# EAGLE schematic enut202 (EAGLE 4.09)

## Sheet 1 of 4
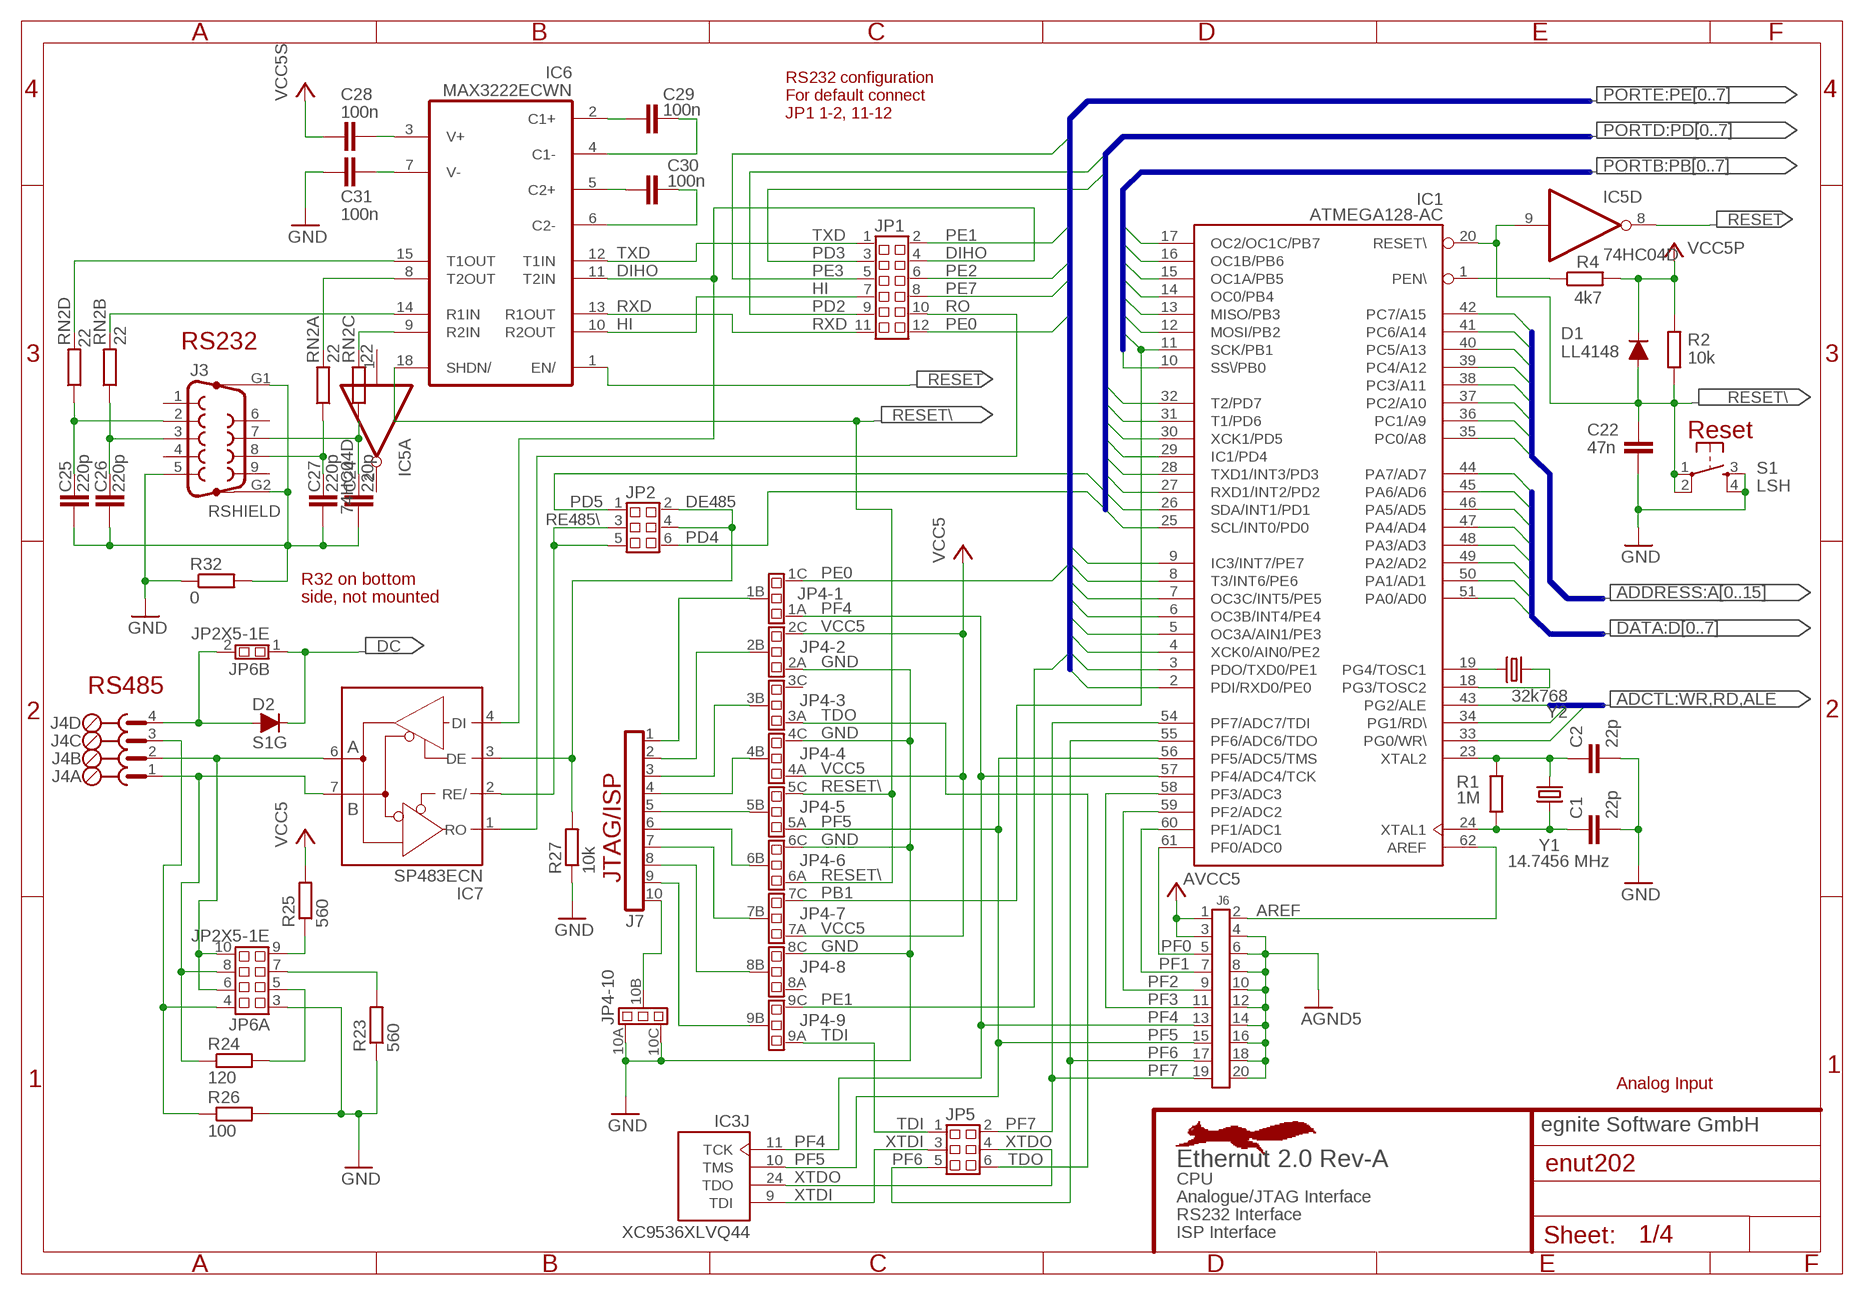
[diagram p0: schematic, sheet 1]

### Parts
C1  22p  C0603  [C0603]
C2  22p  C0603  [C0603]
C22  47n  C0603  [C0603]
C24  220p  C0603  [C0603]
C25  220p  C0603  [C0603]
C26  220p  C0603  [C0603]
C27  220p  C0603  [C0603]
C28  100n  C0603  [C0603]
C29  100n  C0603  [C0603]
C30  100n  C0603  [C0603]
C31  100n  C0603  [C0603]
D1  LL4148  [SOD-80C]
D2  S1G  [SMB]
IC1  ATMEGA128-AC  [TQFP64]
IC3  XC9536XLVQ44  [VQFP44]
IC5  74HC04D  [SO14]
IC6  MAX3222ECWN  [SO18W]
IC7  SP483ECN  [SOIC8]
J3  SUBD9F  [SUBD9F]
J4  MINISK  [MINISK]
J6  PIN2X10-2.54  [SLLP2X10]
J7  ML10A  [ML10A]
JP1  JP2X6  [SLY2X6]
JP2  JP2X3  [SLY2X3]
JP4  JP10X3  [SLY3X10]
JP5  JP2X3  [SLY2X3]
JP6  JP2X5-1E  [SLY2X5]
R1  1M  R0603  [R0603]
R2  10k  R0603  [R0603]
R4  4k7  R0603  [R0603]
R23  560  R1206  [R1206]
R24  120  R1206  [R1206]
R25  560  R1206  [R1206]
R26  100  R1206  [R1206]
R27  10k  R0603  [R0603]
R32  0  R0603  [R0603]
RN2  22  CAY16  [CAY16]
S1  LSH  [LSH]
Y1  14.7456 MHz  CRYSTALHC49SM  [HC49SM]
Y2  32k768  CRYSTAL-TC38  [TC38]

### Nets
A8 [AddrbusH]: IC1.35(PC0/A8) ; also sheet 2
A9 [AddrbusH]: IC1.36(PC1/A9) ; also sheet 2
A10 [AddrbusH]: IC1.37(PC2/A10) ; also sheet 2
A11 [AddrbusH]: IC1.38(PC3/A11) ; also sheet 2
A12 [AddrbusH]: IC1.39(PC4/A12) ; also sheet 2
A13 [AddrbusH]: IC1.40(PC5/A13) ; also sheet 2
A14 [AddrbusH]: IC1.41(PC6/A14) ; also sheet 2
A15 [AddrbusH]: IC1.42(PC7/A15) ; also sheet 2
AGND5: J6.4 J6.6 J6.8 J6.10 J6.12 J6.14 J6.16 J6.18 J6.20 ; also sheet 4
ALE: IC1.43(PG2/ALE) ; also sheet 2
AREF: IC1.62(AREF) J6.2
AVCC5: J6.1 J6.3 ; also sheet 4
D0 [Databus]: IC1.51(PA0/AD0) ; also sheet 2,3
D1 [Databus]: IC1.50(PA1/AD1) ; also sheet 2,3
D2 [Databus]: IC1.49(PA2/AD2) ; also sheet 2,3
D3 [Databus]: IC1.48(PA3/AD3) ; also sheet 2,3
D4 [Databus]: IC1.47(PA4/AD4) ; also sheet 2,3
D5 [Databus]: IC1.46(PA5/AD5) ; also sheet 2,3
D6 [Databus]: IC1.45(PA6/AD6) ; also sheet 2,3
D7 [Databus]: IC1.44(PA7/AD7) ; also sheet 2,3
DC: D2.C JP6.1 ; also sheet 2,4
DCX: D2.A J4.4 JP6.2
DE485: IC7.3(DE) JP2.2 JP2.4 R27.2
DIHO: IC6.11(T2IN) IC7.4(DI) JP1.4
GND: C1.2 C2.2 C22.2 C31.1 J3.5 JP4.2A(-2:A) JP4.4C(-4:C) JP4.6C(-6:C) JP4.8C(-8:C) JP4.10A(-10:A) JP4.10C(-10:C) JP6.3 R23.1 R26.2 R27.1 R32.1 S1.3(S) S1.4(S1) ; also sheet 2,3,4
HI: IC6.10(R2OUT) JP1.7
N$1: C28.2 IC6.3(V+)
N$6: C2.1 IC1.23(XTAL2) R1.2 Y1.P$2
N$7: IC1.19(PG4/TOSC1) Y2.2
N$10: C1.1 IC1.24(XTAL1) R1.1 Y1.P$1
N$15: C31.2 IC6.7(V-)
N$20: JP6.9 R25.1
N$21: J7.1 JP4.1B(-1:B)
N$23: IC1.18(PG3/TOSC2) Y2.1
N$31: C29.1 IC6.2(C1+)
N$38: J7.2 JP4.2B(-2:B)
N$45: J7.4 JP4.4B(-4:B)
N$48: J7.5 JP4.5B(-5:B)
N$49: J7.6 JP4.6B(-6:B)
N$50: J7.7 JP4.7B(-7:B)
N$51: J7.8 JP4.8B(-8:B)
N$52: J7.9 JP4.9B(-9:B)
N$56: C29.2 IC6.4(C1-)
N$57: C30.2 IC6.6(C2-)
N$58: C30.1 IC6.5(C2+)
N$59: J4.3 JP6.4 R26.1
N$60: C24.1 J3.7 RN2.3
N$61: C27.1 J3.8 RN2.1
N$62: C25.1 J3.2 RN2.4
N$63: C26.1 J3.3 RN2.2
N$65: IC6.15(T1OUT) RN2.5
N$66: IC6.8(T2OUT) RN2.8
N$67: IC6.14(R1IN) RN2.7
N$68: JP6.7 R23.2
N$69: IC6.9(R2IN) RN2.6
N$70: JP6.5 R24.2
N$73: J7.10 JP4.10B(-10:B)
PB0: IC1.10(SS\/PB0) ; also sheet 2
PB1: IC1.11(SCK/PB1) JP4.7C(-7:C) ; also sheet 2
PB2: IC1.12(MOSI/PB2) ; also sheet 2
PB3: IC1.13(MISO/PB3) ; also sheet 2
PB4: IC1.14(OC0/PB4) ; also sheet 2
PB5: IC1.15(OC1A/PB5) ; also sheet 2
PB6: IC1.16(OC1B/PB6) ; also sheet 2
PB7: IC1.17(OC2/OC1C/PB7) ; also sheet 2
PD0: IC1.25(SCL/INT0/PD0) ; also sheet 2
PD1: IC1.26(SDA/INT1/PD1) ; also sheet 2
PD2: IC1.27(RXD1/INT2/PD2) JP1.9 ; also sheet 2
PD3: IC1.28(TXD1/INT3/PD3) JP1.3 ; also sheet 2
PD4: IC1.29(IC1/PD4) JP2.6 ; also sheet 2
PD5: IC1.30(XCK1/PD5) JP2.1 ; also sheet 2
PD6: IC1.31(T1/PD6) ; also sheet 2
PD7: IC1.32(T2/PD7) ; also sheet 2
PE0: IC1.2(PDI/RXD0/PE0) JP1.12 JP4.1C(-1:C) ; also sheet 2
PE1: IC1.3(PDO/TXD0/PE1) JP1.2 JP4.9C(-9:C) ; also sheet 2
PE2: IC1.4(XCK0/AIN0/PE2) JP1.6 ; also sheet 2
PE3: IC1.5(OC3A/AIN1/PE3) JP1.5 ; also sheet 2,3
PE4: IC1.6(OC3B/INT4/PE4) ; also sheet 2
PE5: IC1.7(OC3C/INT5/PE5) ; also sheet 2,3
PE6: IC1.8(T3/INT6/PE6) ; also sheet 2
PE7: IC1.9(IC3/INT7/PE7) JP1.8 ; also sheet 2,3
PEN\: IC1.1(PEN\) R4.1
PF0: IC1.61(PF0/ADC0) J6.5
PF1: IC1.60(PF1/ADC1) J6.7
PF2: IC1.59(PF2/ADC2) J6.9
PF3: IC1.58(PF3/ADC3) J6.11
PF4: IC1.57(PF4/ADC4/TCK) IC3.11(TCK) J6.13 JP4.1A(-1:A)
PF5: IC1.56(PF5/ADC5/TMS) IC3.10(TMS) J6.15 JP4.5A(-5:A)
PF6: IC1.55(PF6/ADC6/TDO) J6.17 JP5.5
PF7: IC1.54(PF7/ADC7/TDI) J6.19 JP5.2
RD\: IC1.34(PG1/RD\) ; also sheet 2,3
RE485\: IC7.2(RE/) JP2.3 JP2.5
RESET: IC5.8(D:O) IC6.1(EN/) ; also sheet 3
RESET\: C22.1 D1.A IC1.20(RESET\) IC5.9(D:I) IC6.18(SHDN/) JP4.5C(-5:C) JP4.6A(-6:A) R2.1 S1.1(P) S1.2(P1) ; also sheet 2
RO: IC7.1(RO) JP1.10
RS485A: IC7.6(A) J4.2 JP6.6 JP6.10
RS485B: IC7.7(B) J4.1 JP6.8 R24.1
RSHIELD: C24.2 C25.2 C26.2 C27.2 J3.G1 J3.G2 R32.2
RXD: IC6.13(R1OUT) JP1.11
TDI: JP4.9A(-9:A) JP5.1
TDO: JP4.3A(-3:A) JP5.6
TDOX: J7.3 JP4.3B(-3:B)
TXD: IC6.12(T1IN) JP1.1
VCC5: JP4.2C(-2:C) JP4.4A(-4:A) JP4.7A(-7:A) R25.2 ; also sheet 2,4
VCC5P: D1.C R2.2 R4.2 ; also sheet 4
VCC5S: C28.1 ; also sheet 4
WR\: IC1.33(PG0/WR\) ; also sheet 2,3
XTDI: IC3.9(TDI) JP5.3
XTDO: IC3.24(TDO) JP5.4
Unconnected: IC5.3(B:I) IC5.4(B:O) IC5.5(C:I) IC5.6(C:O) IC5.10(E:O) IC5.11(E:I) IC5.12(F:O) IC5.13(F:I) J3.1 J3.4 J3.6 J3.9 JP4.3C(-3:C) JP4.8A(-8:A)

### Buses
DATA:D[0..7]
ADDRESS:A[0..15]
ADCTL:WR\,RD\,ALE
PORTB:PB[0..7]
PORTD:PD[0..7]
PORTE:PE[0..7]

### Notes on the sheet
- RS232 configuration
- For default connect
- JP1 1-2, 11-12
- RS232
- Reset
- R32 on bottom
- side, not mounted
- RS485
- JTAG/ISP
- Analog Input
- egnite Software GmbH
- Ethernut 2.0 Rev-A
- CPU
- Analogue/JTAG Interface
- RS232 Interface
- ISP Interface

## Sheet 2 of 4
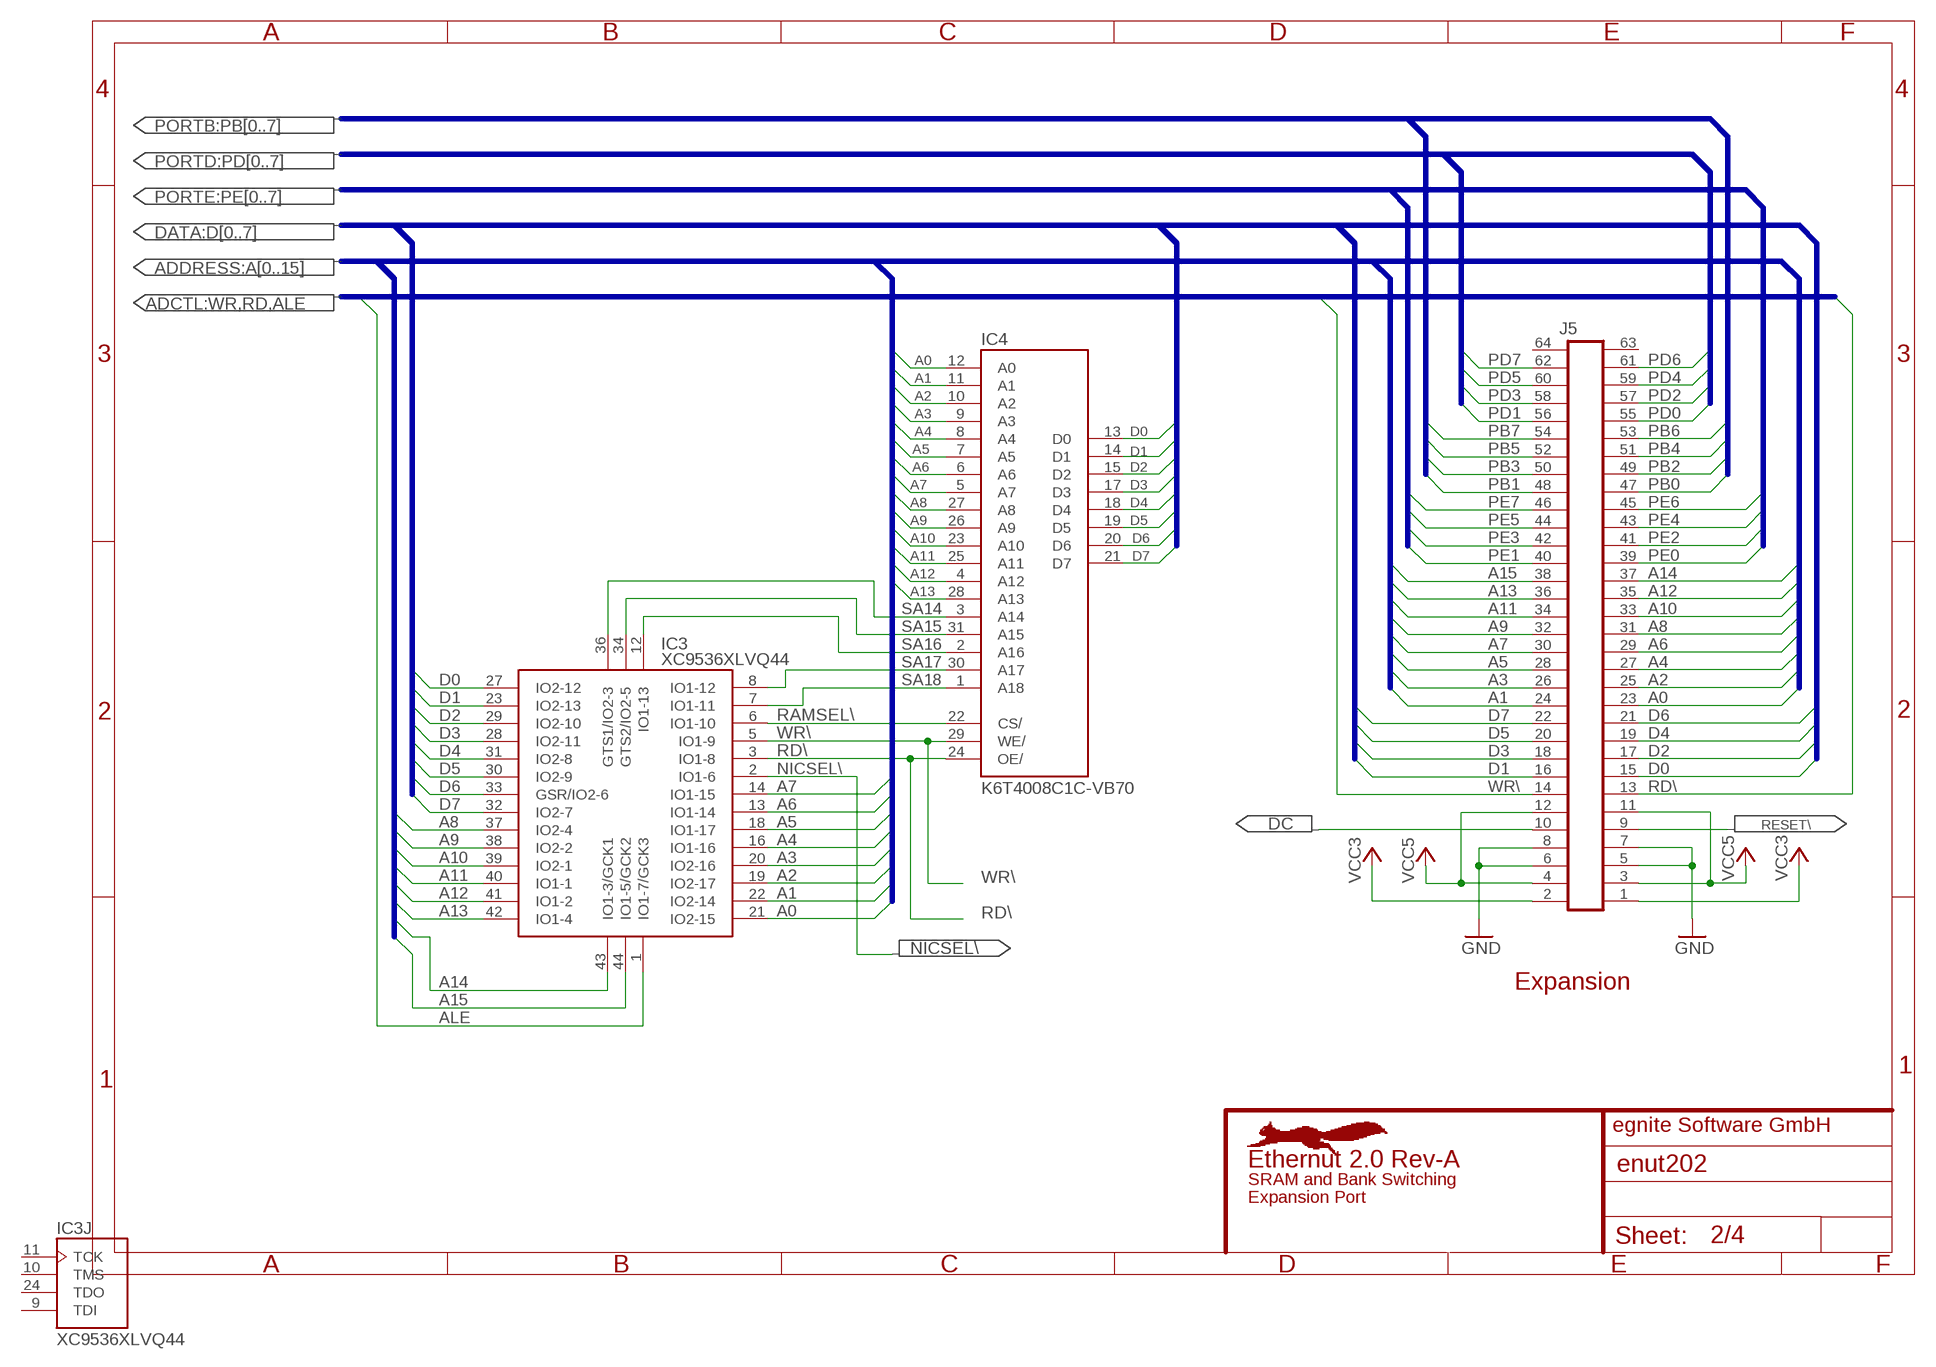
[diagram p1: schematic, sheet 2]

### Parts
IC4  K6T4008C1C-VB70  [TSOP2-32]
J5  NUTEXP  [NUTEXP]

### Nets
A0: IC3.21(IO2-15) IC4.12(A0) J5.23 ; also sheet 3
A1: IC3.22(IO2-14) IC4.11(A1) J5.24 ; also sheet 3
A2: IC3.19(IO2-17) IC4.10(A2) J5.25 ; also sheet 3
A3: IC3.20(IO2-16) IC4.9(A3) J5.26 ; also sheet 3
A4: IC3.16(IO1-16) IC4.8(A4) J5.27 ; also sheet 3
A5: IC3.18(IO1-17) IC4.7(A5) J5.28
A6: IC3.13(IO1-14) IC4.6(A6) J5.29
A7: IC3.14(IO1-15) IC4.5(A7) J5.30
A8 [AddrbusH]: IC3.37(IO2-4) IC4.27(A8) J5.31 ; also sheet 1
A9 [AddrbusH]: IC3.38(IO2-2) IC4.26(A9) J5.32 ; also sheet 1
A10 [AddrbusH]: IC3.39(IO2-1) IC4.23(A10) J5.33 ; also sheet 1
A11 [AddrbusH]: IC3.40(IO1-1) IC4.25(A11) J5.34 ; also sheet 1
A12 [AddrbusH]: IC3.41(IO1-2) IC4.4(A12) J5.35 ; also sheet 1
A13 [AddrbusH]: IC3.42(IO1-4) IC4.28(A13) J5.36 ; also sheet 1
A14 [AddrbusH]: IC3.43(IO1-3/GCK1) J5.37 ; also sheet 1
A15 [AddrbusH]: IC3.44(IO1-5/GCK2) J5.38 ; also sheet 1
ALE: IC3.1(IO1-7/GCK3) ; also sheet 1
D0 [Databus]: IC3.27(IO2-12) IC4.13(D0) J5.15 ; also sheet 1,3
D1 [Databus]: IC3.23(IO2-13) IC4.14(D1) J5.16 ; also sheet 1,3
D2 [Databus]: IC3.29(IO2-10) IC4.15(D2) J5.17 ; also sheet 1,3
D3 [Databus]: IC3.28(IO2-11) IC4.17(D3) J5.18 ; also sheet 1,3
D4 [Databus]: IC3.31(IO2-8) IC4.18(D4) J5.19 ; also sheet 1,3
D5 [Databus]: IC3.30(IO2-9) IC4.19(D5) J5.20 ; also sheet 1,3
D6 [Databus]: IC3.33(GSR/IO2-6) IC4.20(D6) J5.21 ; also sheet 1,3
D7 [Databus]: IC3.32(IO2-7) IC4.21(D7) J5.22 ; also sheet 1,3
DC: J5.10 ; also sheet 1,4
GND: J5.5 J5.6 J5.7 J5.8 ; also sheet 1,3,4
NICSEL\: IC3.2(IO1-6) ; also sheet 3
PB0: J5.47 ; also sheet 1
PB1: J5.48 ; also sheet 1
PB2: J5.49 ; also sheet 1
PB3: J5.50 ; also sheet 1
PB4: J5.51 ; also sheet 1
PB5: J5.52 ; also sheet 1
PB6: J5.53 ; also sheet 1
PB7: J5.54 ; also sheet 1
PD0: J5.55 ; also sheet 1
PD1: J5.56 ; also sheet 1
PD2: J5.57 ; also sheet 1
PD3: J5.58 ; also sheet 1
PD4: J5.59 ; also sheet 1
PD5: J5.60 ; also sheet 1
PD6: J5.61 ; also sheet 1
PD7: J5.62 ; also sheet 1
PE0: J5.39 ; also sheet 1
PE1: J5.40 ; also sheet 1
PE2: J5.41 ; also sheet 1
PE3: J5.42 ; also sheet 1,3
PE4: J5.43 ; also sheet 1
PE5: J5.44 ; also sheet 1,3
PE6: J5.45 ; also sheet 1
PE7: J5.46 ; also sheet 1,3
RAMSEL\: IC3.6(IO1-10) IC4.22(CS/)
RD\: IC3.3(IO1-8) IC4.24(OE/) J5.13 ; also sheet 1,3
RESET\: J5.9 ; also sheet 1
SA14: IC3.36(GTS1/IO2-3) IC4.3(A14)
SA15: IC3.34(GTS2/IO2-5) IC4.31(A15)
SA16: IC3.12(IO1-13) IC4.2(A16)
SA17: IC3.8(IO1-12) IC4.30(A17)
SA18: IC3.7(IO1-11) IC4.1(A18)
VCC3: J5.1 J5.2 ; also sheet 4
VCC5: J5.3 J5.4 J5.11 J5.12 ; also sheet 1,4
WR\: IC3.5(IO1-9) IC4.29(WE/) J5.14 ; also sheet 1,3
Unconnected: J5.63 J5.64

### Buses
ADDRESS:A[0..15]
DATA:D[0..7]
ADCTL:WR\,RD\,ALE
PORTE:PE[0..7]
PORTD:PD[0..7]
PORTB:PB[0..7]

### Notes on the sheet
- Expansion
- egnite Software GmbH
- Ethernut 2.0 Rev-A
- SRAM and Bank Switching
- Expansion Port

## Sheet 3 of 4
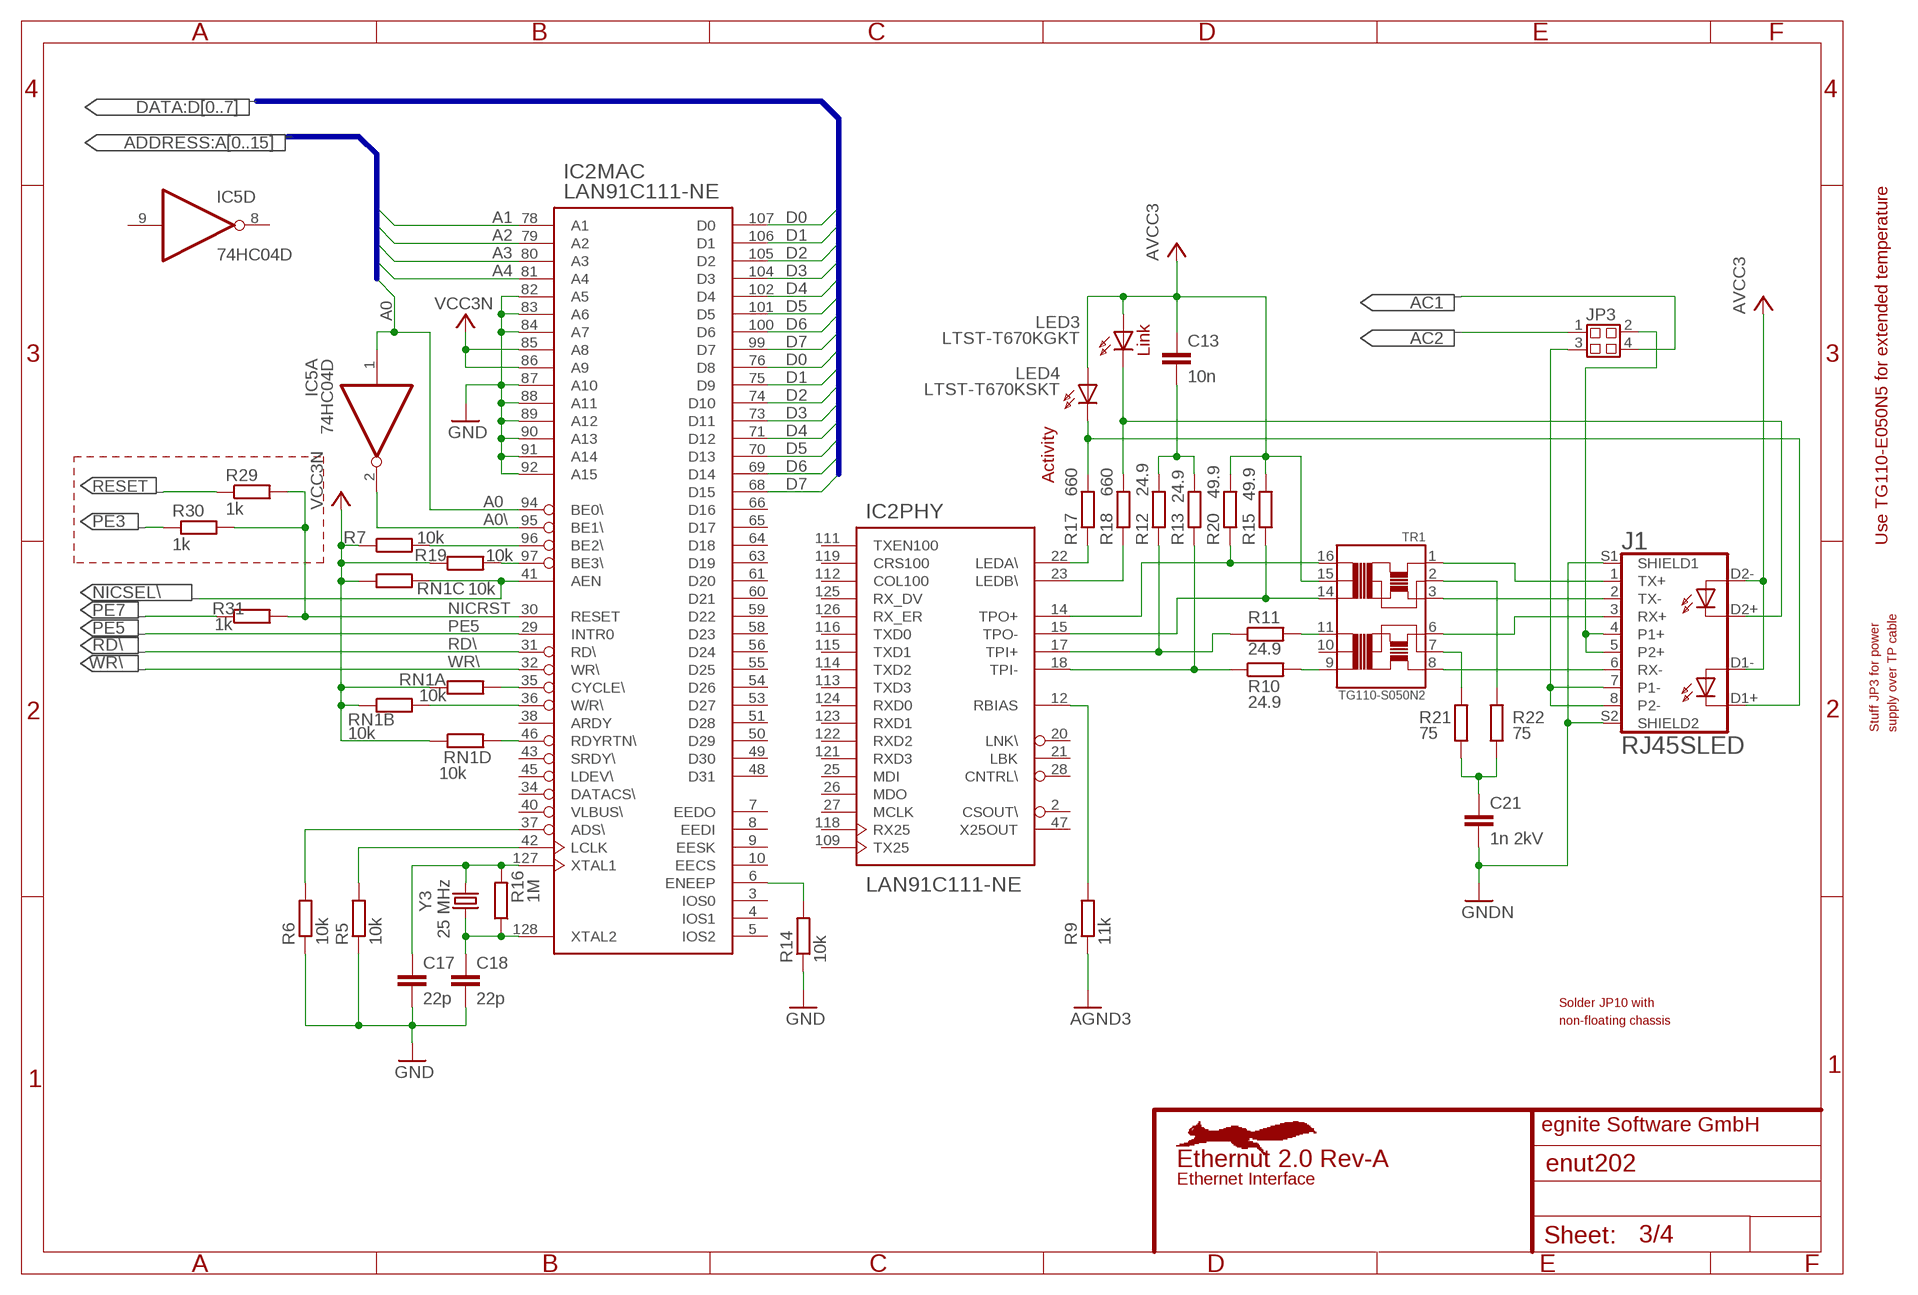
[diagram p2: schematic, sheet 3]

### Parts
C13  10n  C0603  [C0603]
C17  22p  C0603  [C0603]
C18  22p  C0603  [C0603]
C21  1n 2kV  C5.0  [C5.0]
IC2  LAN91C111-NE  [TQFP128]
J1  RJ45SLED  [RJ45S]
JP3  JP2X2  [SLY2X2]
LED3  LTST-T670KGKT  [P-LCC-2]
LED4  LTST-T670KSKT  [P-LCC-2]
R5  10k  R0603  [R0603]
R6  10k  R0603  [R0603]
R7  10k  R0603  [R0603]
R9  11k  R0603  [R0603]
R10  24.9  R0603  [R0603]
R11  24.9  R0603  [R0603]
R12  24.9  R0603  [R0603]
R13  24.9  R0603  [R0603]
R14  10k  R0603  [R0603]
R15  49.9  R0603  [R0603]
R16  1M  R0603  [R0603]
R17  660  R0603  [R0603]
R18  660  R0603  [R0603]
R19  10k  R0603  [R0603]
R20  49.9  R0603  [R0603]
R21  75  R1206  [R1206]
R22  75  R1206  [R1206]
R29  1k  R0603  [R0603]
R30  1k  R0603  [R0603]
R31  1k  R0603  [R0603]
RN1  10k  CAY16  [CAY16]
TR1  TG110-S050N2  [SOIC16-12TR]
Y3  25 MHz  CRYSTALHC49SM  [HC49SM]

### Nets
A0: IC2.94(MAC:BE0\) IC5.1(A:I) ; also sheet 2
A0\: IC2.95(MAC:BE1\) IC5.2(A:O)
A1: IC2.78(MAC:A1) ; also sheet 2
A2: IC2.79(MAC:A2) ; also sheet 2
A3: IC2.80(MAC:A3) ; also sheet 2
A4: IC2.81(MAC:A4) ; also sheet 2
AC1 [Supply1A]: JP3.4 ; also sheet 4
AC2 [Supply1A]: JP3.1 ; also sheet 4
AGND3: R9.1 ; also sheet 4
AVCC3: C13.1 J1.D1-(A1) J1.D2-(A2) LED3.A LED4.A R15.2 R20.2 TR1.15 ; also sheet 4
BE2\: IC2.96(MAC:BE2\) R7.2
CYCLE\: IC2.35(MAC:CYCLE\) RN1.8
D0 [Databus]: IC2.76(MAC:D8) IC2.107(MAC:D0) ; also sheet 1,2
D1 [Databus]: IC2.75(MAC:D9) IC2.106(MAC:D1) ; also sheet 1,2
D2 [Databus]: IC2.74(MAC:D10) IC2.105(MAC:D2) ; also sheet 1,2
D3 [Databus]: IC2.73(MAC:D11) IC2.104(MAC:D3) ; also sheet 1,2
D4 [Databus]: IC2.71(MAC:D12) IC2.102(MAC:D4) ; also sheet 1,2
D5 [Databus]: IC2.70(MAC:D13) IC2.101(MAC:D5) ; also sheet 1,2
D6 [Databus]: IC2.69(MAC:D14) IC2.100(MAC:D6) ; also sheet 1,2
D7 [Databus]: IC2.68(MAC:D15) IC2.99(MAC:D7) ; also sheet 1,2
ENEEP: IC2.6(MAC:ENEEP) R14.2
GND: C17.2 C18.2 IC2.82(MAC:A5) IC2.83(MAC:A6) IC2.84(MAC:A7) IC2.87(MAC:A10) IC2.88(MAC:A11) IC2.89(MAC:A12) IC2.90(MAC:A13) IC2.91(MAC:A14) IC2.92(MAC:A15) R5.1 R6.1 R14.1 ; also sheet 1,2,4
GNDN: C21.2 J1.S1(SHIELD1) J1.S2(SHIELD2)
LCLK: IC2.42(MAC:LCLK) R5.2
LEDA\: J1.D1+(C1) LED4.C R17.2
LEDB\: J1.D2+(C2) LED3.C R18.2
N$4: IC2.37(MAC:ADS\) R6.2
N$5: J1.1(TX+) TR1.1
N$12: J1.2(TX-) TR1.3
N$16: IC2.97(MAC:BE3\) R19.2
N$22: J1.3(RX+) TR1.6
N$24: J1.6(RX-) TR1.8
N$25: IC2.12(PHY:RBIAS) R9.2
N$26: R21.2 TR1.7
N$27: R10.2 TR1.9
N$32: R22.2 TR1.2
N$33: R11.2 TR1.11
N$44: C21.1 R21.1 R22.1
NICRST: IC2.30(MAC:RESET) R29.2 R30.2 R31.2
NICSEL\: IC2.41(MAC:AEN) RN1.6 ; also sheet 2
NICWR\: IC2.36(MAC:W/R\) RN1.7
NLEDA\: IC2.22(PHY:LEDA\) R17.1
NLEDB\: IC2.23(PHY:LEDB\) R18.1
NXTAL1: C17.1 IC2.127(MAC:XTAL1) R16.2 Y3.P$2
NXTAL2: C18.1 IC2.128(MAC:XTAL2) R16.1 Y3.P$1
PE3: R30.1 ; also sheet 1,2
PE5: IC2.29(MAC:INTR0) ; also sheet 1,2
PE7: R31.1 ; also sheet 1,2
POE+ [Supply1A]: J1.7(P1-) J1.8(P2-) JP3.3
POE- [Supply1A]: J1.4(P1+) J1.5(P2+) JP3.2
RD\: IC2.31(MAC:RD\) ; also sheet 1,2
RDYRTN\: IC2.46(MAC:RDYRTN\) RN1.5
RESET: R29.1 ; also sheet 1
RRCUP: C13.2 R12.2 R13.2
TPI+: IC2.17(PHY:TPI+) R11.1 R12.1
TPI-: IC2.18(PHY:TPI-) R10.1 R13.1
TPO+: IC2.14(PHY:TPO+) R20.1 TR1.16
TPO-: IC2.15(PHY:TPO-) R15.1 TR1.14
VCC3N: IC2.85(MAC:A8) IC2.86(MAC:A9) R7.1 R19.1 RN1.1 RN1.2 RN1.3 RN1.4 ; also sheet 4
WR\: IC2.32(MAC:WR\) ; also sheet 1,2
Unconnected: TR1.10

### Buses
DATA:D[0..7]
ADDRESS:A[0..15]

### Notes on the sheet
- Link
- Activity
- Use TG110-E050N5 for extended temperature
- Stuff JP3 for power | supply over TP cable
- Solder JP10 with
- non-floating chassis
- egnite Software GmbH
- Ethernut 2.0 Rev-A
- Ethernet Interface

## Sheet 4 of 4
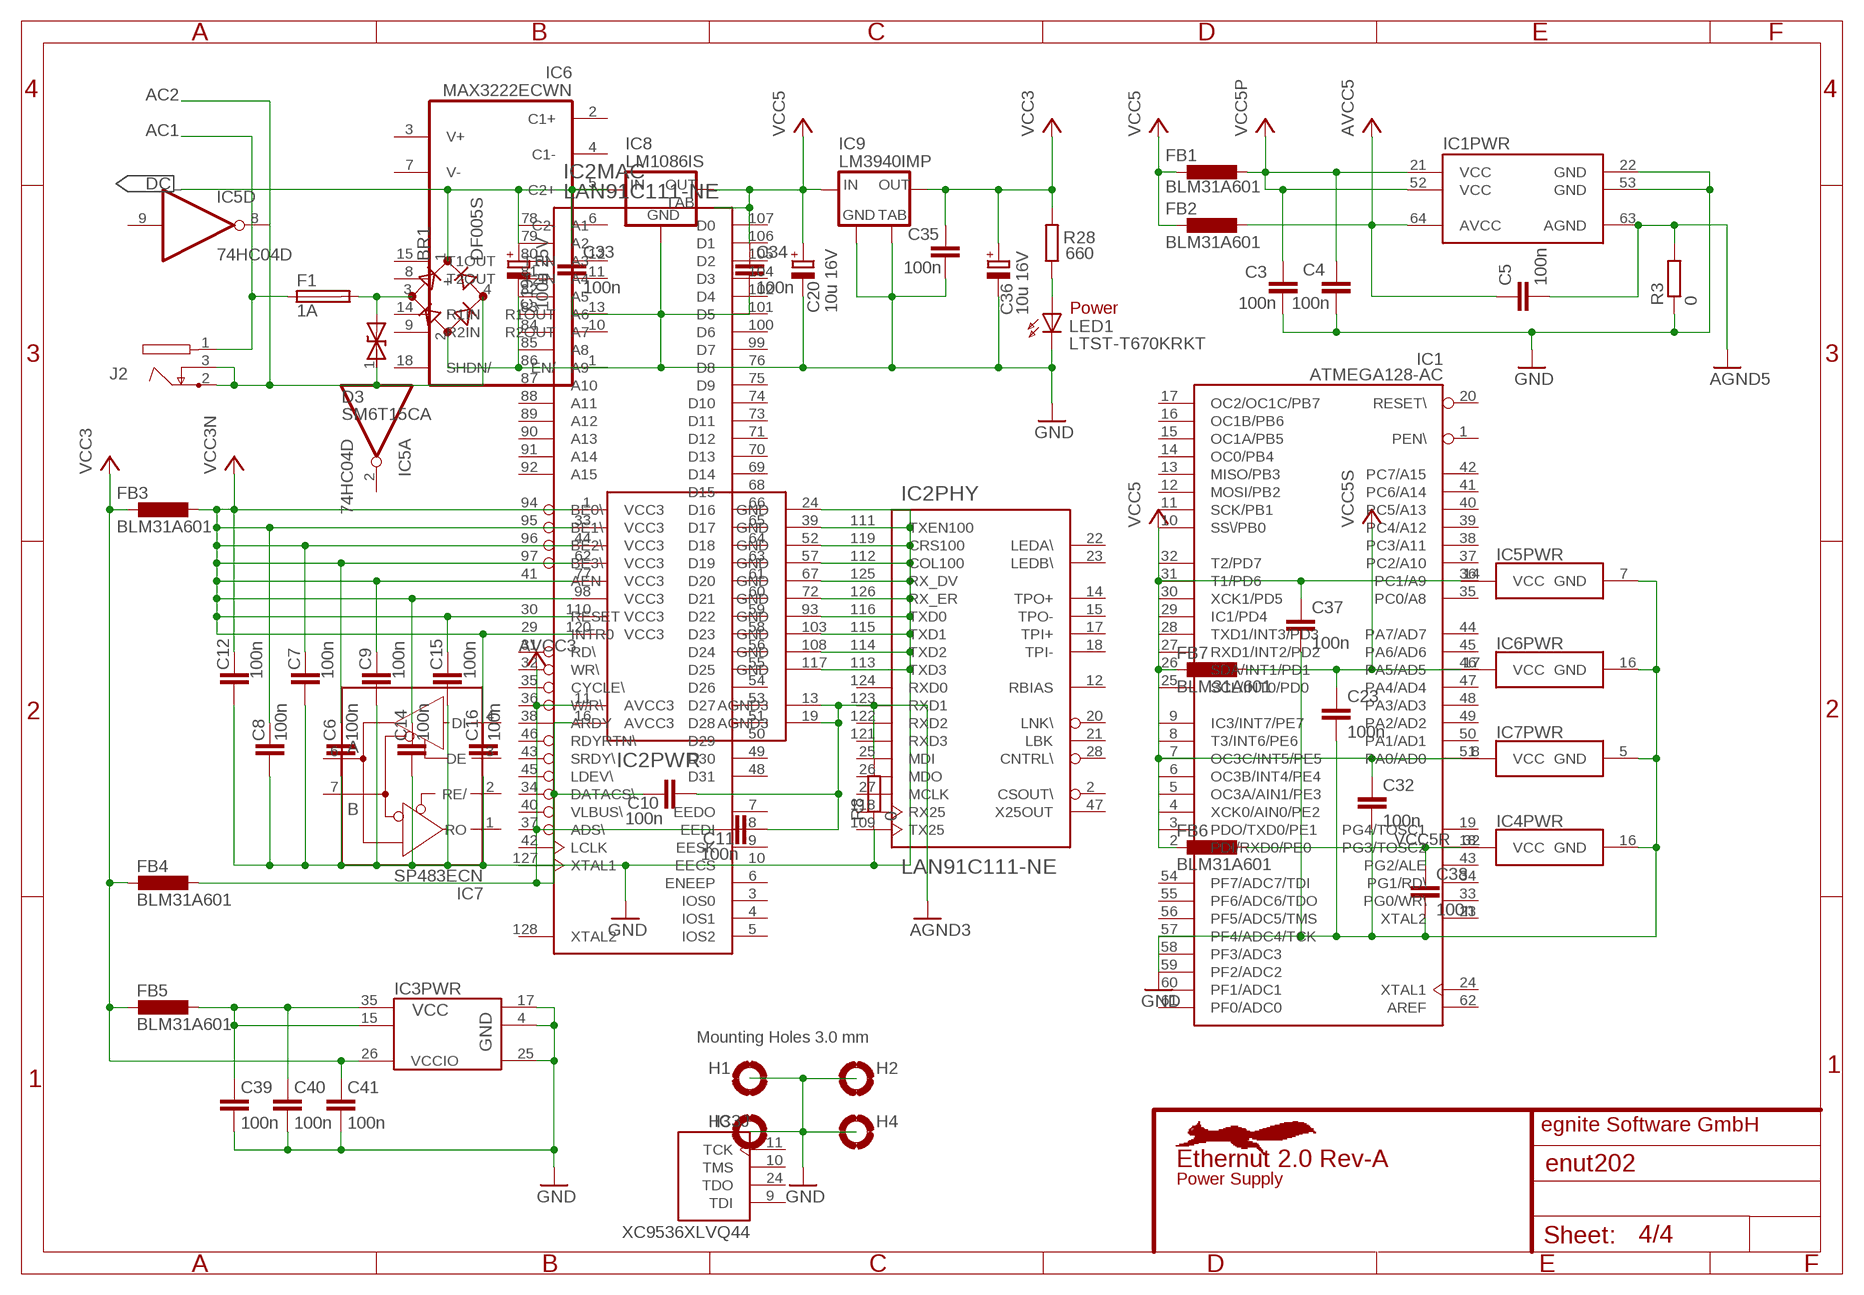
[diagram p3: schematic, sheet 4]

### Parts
BR1  DF005S  [DFS]
C3  100n  C0603  [C0603]
C4  100n  C0603  [C0603]
C5  100n  C0603  [C0603]
C6  100n  C0603  [C0603]
C7  100n  C0603  [C0603]
C8  100n  C0603  [C0603]
C9  100n  C0603  [C0603]
C10  100n  C0603  [C0603]
C11  100n  C0603  [C0603]
C12  100n  C0603  [C0603]
C14  100n  C0603  [C0603]
C15  100n  C0603  [C0603]
C16  100n  C0603  [C0603]
C19  100u 25V  ALUCAP6.3  [ALUC6.3]
C20  10u 16V  ALUCAP4.0  [ALUC4.0]
C23  100n  C0603  [C0603]
C32  100n  C0603  [C0603]
C33  100n  C0603  [C0603]
C34  100n  C0603  [C0603]
C35  100n  C0603  [C0603]
C36  10u 16V  ALUCAP4.0  [ALUC4.0]
C37  100n  C0603  [C0603]
C38  100n  C0603  [C0603]
C39  100n  C0603  [C0603]
C40  100n  C0603  [C0603]
C41  100n  C0603  [C0603]
D3  SM6T15CA  SM6T  [SMB]
F1  1A  OMNI-BLOK  [OMNI-BLOK]
FB1  BLM31A601  BLM31A  [BLM31]
FB2  BLM31A601  BLM31A  [BLM31]
FB3  BLM31A601  BLM31A  [BLM31]
FB4  BLM31A601  BLM31A  [BLM31]
FB5  BLM31A601  BLM31A  [BLM31]
FB6  BLM31A601  BLM31A  [BLM31]
FB7  BLM31A601  BLM31A  [BLM31]
H1  MOUNT3  [MOUNT3]
H2  MOUNT3  [MOUNT3]
H3  MOUNT3  [MOUNT3]
H4  MOUNT3  [MOUNT3]
IC8  LM1086IS  [DDPAK-ST]
IC9  LM3940IMP  [SOT-223]
J2  DC2.1  [DC2.1]
LED1  LTST-T670KRKT  [P-LCC-2]
R3  0  R0603  [R0603]
R8  0  R0603  [R0603]
R28  660  R0603  [R0603]

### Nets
AC1 [Supply1A]: F1.1 J2.1 ; also sheet 3
AC2 [Supply1A]: BR1.4(AC2) D3.A J2.2 J2.3 ; also sheet 3
ACF: BR1.3(AC1) D3.C F1.2
AGND3: C10.2 C11.2 IC2.13(PWR:AGND3) IC2.19(PWR:AGND3) R8.2 ; also sheet 3
AGND5: C5.2 IC1.63(AGND) R3.2 ; also sheet 1
AVCC3: C10.1 C11.1 FB4.1 IC2.11(PWR:AVCC3) IC2.16(PWR:AVCC3) ; also sheet 3
AVCC5: C5.1 FB2.2 IC1.64(AVCC) ; also sheet 1
DC: BR1.1(+) C19.+ C33.1 IC8.3(IN) ; also sheet 1,2
GND: BR1.2(-) C3.2 C4.2 C6.2 C7.2 C8.2 C9.2 C12.2 C14.2 C15.2 C16.2 C19.- C20.- C23.2 C32.2 C33.2 C34.2 C35.2 C36.- C37.2 C38.2 C39.2 C40.2 C41.2 H1.B3,0(MOUNT) H2.B3,0(MOUNT) H3.B3,0(MOUNT) H4.B3,0(MOUNT) IC1.22(GND) IC1.53(GND) IC2.24(PWR:GND) IC2.39(PWR:GND) IC2.52(PWR:GND) IC2.57(PWR:GND) IC2.67(PWR:GND) IC2.72(PWR:GND) IC2.93(PWR:GND) IC2.103(PWR:GND) IC2.108(PWR:GND) IC2.117(PWR:GND) IC3.4(GND) IC3.17(GND) IC3.25(GND) IC4.16(GND) IC5.7(PWR:GND) IC6.16(GND) IC7.5(GND) IC8.1(GND) IC9.2(GND) IC9.4(TAB) LED1.C R3.1 R8.1 ; also sheet 1,2,3
N$43: LED1.A R28.1
VCC3: C35.1 C36.+ C41.1 FB3.1 FB4.2 FB5.2 IC3.26(VCCIO) IC9.3(OUT) R28.2 ; also sheet 2
VCC3N: C6.1 C7.1 C8.1 C9.1 C12.1 C14.1 C15.1 C16.1 FB3.2 IC2.1(PWR:VCC3) IC2.33(PWR:VCC3) IC2.44(PWR:VCC3) IC2.62(PWR:VCC3) IC2.77(PWR:VCC3) IC2.98(PWR:VCC3) IC2.110(PWR:VCC3) IC2.120(PWR:VCC3) ; also sheet 3
VCC3X: C39.1 C40.1 FB5.1 IC3.15(VCCINT) IC3.35(VCCINT)
VCC5: C20.+ C32.1 C34.1 C37.1 FB1.1 FB2.1 FB6.2 FB7.2 IC5.14(PWR:VCC) IC7.8(VCC) IC8.2(OUT) IC8.4(TAB) IC9.1(IN) ; also sheet 1,2
VCC5P: C3.1 C4.1 FB1.2 IC1.21(VCC) IC1.52(VCC) ; also sheet 1
VCC5R: C38.1 FB6.1 IC4.32(VCC)
VCC5S: C23.1 FB7.1 IC6.17(VCC) ; also sheet 1
Unconnected: IC2.2(PHY:CSOUT\) IC2.3(MAC:IOS0) IC2.4(MAC:IOS1) IC2.5(MAC:IOS2) IC2.7(MAC:EEDO) IC2.8(MAC:EEDI) IC2.9(MAC:EESK) IC2.10(MAC:EECS) IC2.20(PHY:LNK\) IC2.21(PHY:LBK) IC2.25(PHY:MDI) IC2.26(PHY:MDO) IC2.27(PHY:MCLK) IC2.28(PHY:CNTRL\) IC2.34(MAC:DATACS\) IC2.38(MAC:ARDY) IC2.40(MAC:VLBUS\) IC2.43(MAC:SRDY\) IC2.45(MAC:LDEV\) IC2.47(PHY:X25OUT) IC2.48(MAC:D31) IC2.49(MAC:D30) IC2.50(MAC:D29) IC2.51(MAC:D28) IC2.53(MAC:D27) IC2.54(MAC:D26) IC2.55(MAC:D25) IC2.56(MAC:D24) IC2.58(MAC:D23) IC2.59(MAC:D22) IC2.60(MAC:D21) IC2.61(MAC:D20) IC2.63(MAC:D19) IC2.64(MAC:D18) IC2.65(MAC:D17) IC2.66(MAC:D16) IC2.109(PHY:TX25) IC2.111(PHY:TXEN100) IC2.112(PHY:COL100) IC2.113(PHY:TXD3) IC2.114(PHY:TXD2) IC2.115(PHY:TXD1) IC2.116(PHY:TXD0) IC2.118(PHY:RX25) IC2.119(PHY:CRS100) IC2.121(PHY:RXD3) IC2.122(PHY:RXD2) IC2.123(PHY:RXD1) IC2.124(PHY:RXD0) IC2.125(PHY:RX_DV) IC2.126(PHY:RX_ER)

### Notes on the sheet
- Power
- Mounting Holes 3.0 mm
- egnite Software GmbH
- Ethernut 2.0 Rev-A
- Power Supply

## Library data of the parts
BR1 = enut202:DF005S
C1-C18 C21-C35 C37-C41 = enut202:C
C19 C20 C36 = enut202:ALUCAP
D1 = enut202:LL4148
D2 = enut202:S1G
D3 = enut202:SM6T: Bidirectional Transient Voltage Suppressor
F1 = enut202:OMNI-BLOK: Littlefuse OMNI-BLOK Fuseholder
FB1-FB7 = enut202:BLM31A: EMI Suppression Filter
H1-H4 = enut202:MOUNT3
IC1 = enut202:ATMEGA128
IC2 = enut202:LAN91C111: 10/100 Non-PCI Ethernet MAC + PHY
IC3 = enut202:XC9536XL: High Performance CPLD 36 macrocells 34 user I/O pins
IC4 = enut202:K6T4008C1C: SRAM 512k x 8
IC5 = enut202:74*04: Hex Negate
IC6 = enut202:MAX3222E
IC7 = enut202:SP483E
IC8 = enut202:LM1086
IC9 = enut202:LM3940
J1 = enut202:RJ45SLED
J2 = enut202:DC
J3 = enut202:SUBD9F
J4 = enut202:MINISK
J5 = enut202:NUTEXP
J6 = enut202:PIN2X10
J7 = enut202:ML10
JP1 = enut202:JP2X6
JP2 JP5 = enut202:JP2X3
JP3 = enut202:JP2X2
JP4 = enut202:JP10X3
JP6 = enut202:JP2X5-1E
LED1 LED3 LED4 = enut202:LTST-T670: SMD LED
R1-R32 = enut202:R
RN1 RN2 = enut202:CAY16
S1 = enut202:LSH
TR1 = enut202:TG110-S050
Y1-Y3 = enut202:CRYSTAL

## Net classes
1 Supply1A: width 0.61 mm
